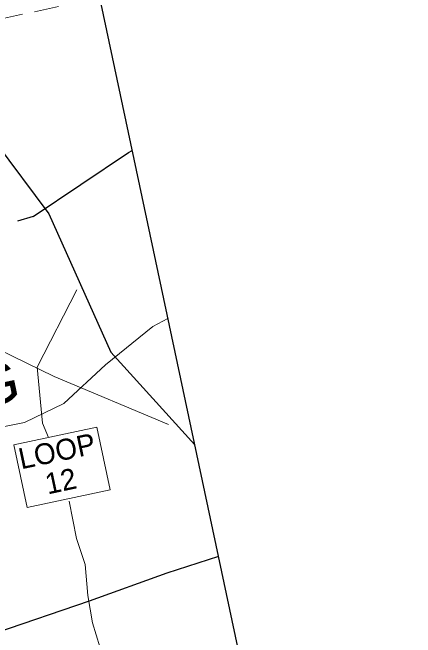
# Model space of a CAD drawing. Extents: x 2357218 to 2371708, y 6973728 to 6980157.
# Drawn here: x 2371609.7 to 2371708, y 6977662.2 to 6977814.7 of the extents above; entities that cross this region are included whole.
import ezdxf

# ---------------------------------------------------------------- set-up
doc = ezdxf.new("R2010")
doc.units = 0
doc.header["$LTSCALE"] = 2
doc.linetypes.add('MEDIUM_DASHED', pattern=[4.5, 3, -1.5])
doc.layers.add('62', color=7, linetype='Continuous', lineweight=13)
doc.layers.add('63', color=7, linetype='Continuous', lineweight=13)

msp = doc.modelspace()

# ---------------------------------------------------------------- linework, layer by layer
at = {"layer": '62', "linetype": 'MEDIUM_DASHED'}
msp.add_line((2371629.67, 6977817.964), (2371191.201, 6977724.765), dxfattribs=at)
at = {"layer": '62', "lineweight": 25}
msp.add_line((2371614.716, 6977764.935), (2371610.853, 6977763.746), dxfattribs=at)
at = {"layer": '62'}
for p, q in [((2371619.865, 6977725.887), (2371599.831, 6977735.614)), ((2371619.865, 6977725.887), (2371647.758, 6977714.148)), ((2371616.966, 6977714.526), (2371618.447, 6977711.023))]:
    msp.add_line(p, q, dxfattribs=at)
at = {"layer": '62', "lineweight": 25}
for points in [[(2371171.482, 6977817.538), (2371268.218, 6977362.432), (2371707.985, 6977455.907), (2371611.249, 6977911.015)], [(2371605.386, 6977783.08), (2371618.494, 6977765.555), (2371633.69, 6977731.838), (2371654.141, 6977709.225)], [(2371614.716, 6977764.935), (2371637.958, 6977780.502), (2371638.885, 6977780.998)], [(2371659.938, 6977681.952), (2371647.349, 6977677.965), (2371628.369, 6977671.057), (2371605.423, 6977663.305), (2371580.264, 6977656.875), (2371551.849, 6977650.836), (2371520.802, 6977643.338), (2371503.25, 6977638.459)]]:
    msp.add_lwpolyline(points, dxfattribs=at)
at = {"layer": '62'}
for points in [[(2371616.966, 6977714.526), (2371615.703, 6977728.155), (2371625.355, 6977747.02)], [(2371524.394, 6977695.264), (2371537.271, 6977698.852), (2371559.74, 6977705.374), (2371580.871, 6977708.9), (2371594.951, 6977711.158), (2371612.626, 6977714.706), (2371622.215, 6977719.277), (2371632.346, 6977728.746), (2371643.913, 6977738.084), (2371647.591, 6977740.041)], [(2371669.776, 6977635.664), (2371660.267, 6977636.565), (2371643.965, 6977638.048), (2371634.547, 6977649.456), (2371631.882, 6977657.01), (2371629.164, 6977665.797), (2371628.025, 6977672.456), (2371627.386, 6977680.002), (2371625.287, 6977686.412), (2371623.525, 6977695.471)]]:
    msp.add_lwpolyline(points, dxfattribs=at)
msp.add_lwpolyline([(2371609.972, 6977709.22), (2371613.216, 6977693.969), (2371633.464, 6977698.273), (2371630.222, 6977713.526)], close=True, dxfattribs=at)
at = {"layer": '63', "linetype": 'MEDIUM_DASHED'}
msp.add_line((2371629.67, 6977817.964), (2371191.201, 6977724.765), dxfattribs=at)
at = {"layer": '63', "lineweight": 25}
msp.add_line((2371614.716, 6977764.935), (2371610.853, 6977763.746), dxfattribs=at)
at = {"layer": '63'}
for p, q in [((2371619.865, 6977725.887), (2371599.831, 6977735.614)), ((2371619.865, 6977725.887), (2371647.758, 6977714.148)), ((2371616.966, 6977714.526), (2371618.447, 6977711.023))]:
    msp.add_line(p, q, dxfattribs=at)
at = {"layer": '63', "lineweight": 25}
for points in [[(2371171.482, 6977817.538), (2371268.218, 6977362.432), (2371707.985, 6977455.907), (2371611.249, 6977911.015)], [(2371605.386, 6977783.08), (2371618.494, 6977765.555), (2371633.69, 6977731.838), (2371654.141, 6977709.225)], [(2371614.716, 6977764.935), (2371637.958, 6977780.502), (2371638.885, 6977780.998)], [(2371659.938, 6977681.952), (2371647.349, 6977677.965), (2371628.369, 6977671.057), (2371605.423, 6977663.305), (2371580.264, 6977656.875), (2371551.849, 6977650.836), (2371520.802, 6977643.338), (2371503.25, 6977638.459)]]:
    msp.add_lwpolyline(points, dxfattribs=at)
at = {"layer": '63'}
for points in [[(2371616.966, 6977714.526), (2371615.703, 6977728.155), (2371625.355, 6977747.02)], [(2371524.394, 6977695.264), (2371537.271, 6977698.852), (2371559.74, 6977705.374), (2371580.871, 6977708.9), (2371594.951, 6977711.158), (2371612.626, 6977714.706), (2371622.215, 6977719.277), (2371632.346, 6977728.746), (2371643.913, 6977738.084), (2371647.591, 6977740.041)], [(2371669.776, 6977635.664), (2371660.267, 6977636.565), (2371643.965, 6977638.048), (2371634.547, 6977649.456), (2371631.882, 6977657.01), (2371629.164, 6977665.797), (2371628.025, 6977672.456), (2371627.386, 6977680.002), (2371625.287, 6977686.412), (2371623.525, 6977695.471)]]:
    msp.add_lwpolyline(points, dxfattribs=at)
msp.add_lwpolyline([(2371609.972, 6977709.22), (2371613.216, 6977693.969), (2371633.464, 6977698.273), (2371630.222, 6977713.526)], close=True, dxfattribs=at)

# ---------------------------------------------------------------- texts
at = {"layer": '62', "width": 1.1}
msp.add_text('IRVING', height=10.21, rotation=12, dxfattribs=at).set_placement((2371561.625, 6977709.503))
at = {"layer": '62'}
for s, p in [('LOOP', (2371611.775, 6977703.233)), ('12', (2371618.251, 6977697.11))]:
    msp.add_text(s, height=5.099, rotation=12, dxfattribs=at).set_placement(p)
at = {"layer": '63', "width": 1.1}
msp.add_text('IRVING', height=10.21, rotation=12, dxfattribs=at).set_placement((2371561.625, 6977709.503))
at = {"layer": '63'}
for s, p in [('LOOP', (2371611.775, 6977703.233)), ('12', (2371618.251, 6977697.11))]:
    msp.add_text(s, height=5.099, rotation=12, dxfattribs=at).set_placement(p)

doc.saveas('drawing.dxf')
